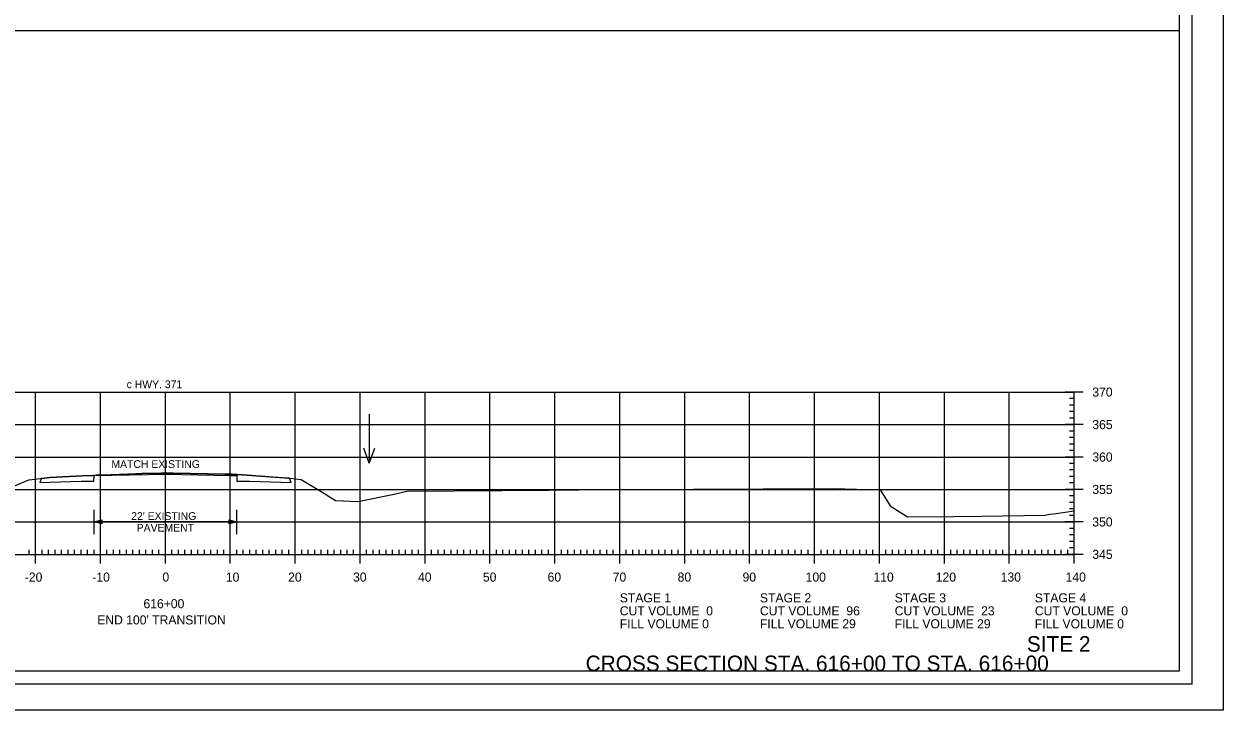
# Model space of a CAD drawing. Extents: x 1368910 to 1369601, y 380116 to 380950.
# Drawn here: x 1369415.8 to 1369600.5, y 380737.1 to 380842.8 of the extents above; entities that cross this region are included whole.
import ezdxf

# ---------------------------------------------------------------- set-up
doc = ezdxf.new("R2010")
doc.units = 0
for name, color, linetype in [('_STAGE 2 CUT', 7, 'Continuous'), ('_STAGE 3 CUT', 7, 'Continuous'), ('Notes', 7, 'Continuous'), ('R_Axis', 7, 'Continuous'), ('R_Axis Annot', 7, 'Continuous'), ('R_Border', 7, 'Continuous'), ('R_Draft', 7, 'Continuous'), ('R_Exist Surface', 7, 'Continuous'), ('R_Grid', 7, 'Continuous'), ('R_No Plot', 7, 'Continuous'), ('R_ROW Annot', 7, 'Continuous'), ('R_Water Annot', 7, 'Continuous')]:
    doc.layers.add(name, color=color, linetype=linetype)

msp = doc.modelspace()

# ---------------------------------------------------------------- linework, layer by layer
at = {"layer": '_STAGE 2 CUT'}
for p, q in [((1369437.59, 380773.62), (1369437.59, 380773.45)), ((1369456.95, 380772.15), (1369456.69, 380772.82))]:
    msp.add_line(p, q, dxfattribs=at)
for points in [[(1369448.57, 380773.41), (1369447.85, 380773.45), (1369447.59, 380773.46), (1369446.77, 380773.48), (1369438.78, 380773.61), (1369437.98, 380773.61), (1369437.69, 380773.62), (1369437.59, 380773.62)], [(1369437.59, 380773.45), (1369447.59, 380773.25), (1369448.59, 380773.23), (1369448.6, 380772.4), (1369450.59, 380772.36), (1369456.95, 380772.15)], [(1369448.57, 380773.4), (1369448.57, 380773.41)], [(1369448.67, 380773.4), (1369448.59, 380773.4), (1369448.57, 380773.4)], [(1369456.69, 380772.82), (1369456.29, 380772.85), (1369450.16, 380773.29), (1369448.67, 380773.4), (1369448.67, 380773.4)]]:
    msp.add_lwpolyline(points, dxfattribs=at)
at = {"layer": '_STAGE 3 CUT'}
for p, q in [((1369437.17, 380773.61), (1369436.89, 380773.61)), ((1369437.3, 380773.61), (1369437.17, 380773.61)), ((1369437.59, 380773.45), (1369437.59, 380773.62)), ((1369418.48, 380772.8), (1369418.23, 380772.15))]:
    msp.add_line(p, q, dxfattribs=at)
for points in [[(1369436.89, 380773.61), (1369433.98, 380773.54), (1369433.01, 380773.5), (1369427.9, 380773.32), (1369426.94, 380773.29), (1369426.53, 380773.27), (1369426.47, 380773.26), (1369424.81, 380773.18), (1369419.8, 380772.94), (1369418.89, 380772.85), (1369418.48, 380772.8)], [(1369437.59, 380773.62), (1369437.38, 380773.62), (1369437.3, 380773.61)], [(1369418.23, 380772.15), (1369424.59, 380772.36), (1369426.58, 380772.4), (1369426.59, 380773.23), (1369437.59, 380773.45)]]:
    msp.add_lwpolyline(points, dxfattribs=at)
at = {"layer": 'R_Axis'}
for p, q in [((1369578.99, 380786.1), (1369576.19, 380786.1)), ((1369577.59, 380785.1), (1369576.89, 380785.1)), ((1369577.59, 380761.1), (1369577.59, 380786.1)), ((1369577.59, 380784.1), (1369576.89, 380784.1)), ((1369577.59, 380783.1), (1369576.89, 380783.1)), ((1369578.99, 380781.1), (1369576.19, 380781.1)), ((1369577.59, 380782.1), (1369576.89, 380782.1)), ((1369577.59, 380780.1), (1369576.89, 380780.1)), ((1369577.59, 380779.1), (1369576.89, 380779.1)), ((1369577.59, 380778.1), (1369576.89, 380778.1)), ((1369578.99, 380776.1), (1369576.19, 380776.1)), ((1369577.59, 380777.1), (1369576.89, 380777.1)), ((1369577.59, 380775.1), (1369576.89, 380775.1)), ((1369577.59, 380774.1), (1369576.89, 380774.1)), ((1369577.59, 380773.1), (1369576.89, 380773.1)), ((1369577.59, 380772.1), (1369576.89, 380772.1)), ((1369578.99, 380771.1), (1369576.19, 380771.1)), ((1369577.59, 380770.1), (1369576.89, 380770.1)), ((1369577.59, 380769.1), (1369576.89, 380769.1)), ((1369577.59, 380768.1), (1369576.89, 380768.1)), ((1369577.59, 380767.1), (1369576.89, 380767.1)), ((1369578.99, 380766.1), (1369576.19, 380766.1)), ((1369577.59, 380765.1), (1369576.89, 380765.1)), ((1369417.59, 380759.7), (1369417.59, 380762.5)), ((1369427.59, 380759.7), (1369427.59, 380762.5)), ((1369437.59, 380759.7), (1369437.59, 380762.5)), ((1369447.59, 380759.7), (1369447.59, 380762.5)), ((1369457.59, 380759.7), (1369457.59, 380762.5)), ((1369467.59, 380759.7), (1369467.59, 380762.5)), ((1369477.59, 380759.7), (1369477.59, 380762.5)), ((1369487.59, 380759.7), (1369487.59, 380762.5)), ((1369497.59, 380759.7), (1369497.59, 380762.5)), ((1369507.59, 380759.7), (1369507.59, 380762.5)), ((1369517.59, 380759.7), (1369517.59, 380762.5)), ((1369527.59, 380759.7), (1369527.59, 380762.5)), ((1369537.59, 380759.7), (1369537.59, 380762.5)), ((1369547.59, 380759.7), (1369547.59, 380762.5)), ((1369557.59, 380759.7), (1369557.59, 380762.5)), ((1369567.59, 380759.7), (1369567.59, 380762.5)), ((1369577.59, 380764.1), (1369576.89, 380764.1)), ((1369577.59, 380763.1), (1369576.89, 380763.1)), ((1369577.59, 380759.7), (1369577.59, 380762.5)), ((1369297.59, 380761.1), (1369577.59, 380761.1)), ((1369416.59, 380761.1), (1369416.59, 380761.8)), ((1369418.59, 380761.1), (1369418.59, 380761.8)), ((1369419.59, 380761.1), (1369419.59, 380761.8)), ((1369420.59, 380761.1), (1369420.59, 380761.8)), ((1369421.59, 380761.1), (1369421.59, 380761.8)), ((1369422.59, 380761.1), (1369422.59, 380761.8)), ((1369423.59, 380761.1), (1369423.59, 380761.8)), ((1369424.59, 380761.1), (1369424.59, 380761.8)), ((1369425.59, 380761.1), (1369425.59, 380761.8)), ((1369426.59, 380761.1), (1369426.59, 380761.8)), ((1369428.59, 380761.1), (1369428.59, 380761.8)), ((1369429.59, 380761.1), (1369429.59, 380761.8)), ((1369430.59, 380761.1), (1369430.59, 380761.8)), ((1369431.59, 380761.1), (1369431.59, 380761.8)), ((1369432.59, 380761.1), (1369432.59, 380761.8)), ((1369433.59, 380761.1), (1369433.59, 380761.8)), ((1369434.59, 380761.1), (1369434.59, 380761.8)), ((1369435.59, 380761.1), (1369435.59, 380761.8)), ((1369436.59, 380761.1), (1369436.59, 380761.8)), ((1369438.59, 380761.1), (1369438.59, 380761.8)), ((1369439.59, 380761.1), (1369439.59, 380761.8)), ((1369440.59, 380761.1), (1369440.59, 380761.8)), ((1369441.59, 380761.1), (1369441.59, 380761.8)), ((1369442.59, 380761.1), (1369442.59, 380761.8)), ((1369443.59, 380761.1), (1369443.59, 380761.8)), ((1369444.59, 380761.1), (1369444.59, 380761.8)), ((1369445.59, 380761.1), (1369445.59, 380761.8)), ((1369446.59, 380761.1), (1369446.59, 380761.8)), ((1369448.59, 380761.1), (1369448.59, 380761.8)), ((1369449.59, 380761.1), (1369449.59, 380761.8)), ((1369450.59, 380761.1), (1369450.59, 380761.8)), ((1369451.59, 380761.1), (1369451.59, 380761.8)), ((1369452.59, 380761.1), (1369452.59, 380761.8)), ((1369453.59, 380761.1), (1369453.59, 380761.8)), ((1369454.59, 380761.1), (1369454.59, 380761.8)), ((1369455.59, 380761.1), (1369455.59, 380761.8)), ((1369456.59, 380761.1), (1369456.59, 380761.8)), ((1369458.59, 380761.1), (1369458.59, 380761.8)), ((1369459.59, 380761.1), (1369459.59, 380761.8)), ((1369460.59, 380761.1), (1369460.59, 380761.8)), ((1369461.59, 380761.1), (1369461.59, 380761.8)), ((1369462.59, 380761.1), (1369462.59, 380761.8)), ((1369463.59, 380761.1), (1369463.59, 380761.8)), ((1369464.59, 380761.1), (1369464.59, 380761.8)), ((1369465.59, 380761.1), (1369465.59, 380761.8)), ((1369466.59, 380761.1), (1369466.59, 380761.8)), ((1369468.59, 380761.1), (1369468.59, 380761.8)), ((1369469.59, 380761.1), (1369469.59, 380761.8)), ((1369470.59, 380761.1), (1369470.59, 380761.8)), ((1369471.59, 380761.1), (1369471.59, 380761.8)), ((1369472.59, 380761.1), (1369472.59, 380761.8)), ((1369473.59, 380761.1), (1369473.59, 380761.8)), ((1369474.59, 380761.1), (1369474.59, 380761.8)), ((1369475.59, 380761.1), (1369475.59, 380761.8)), ((1369476.59, 380761.1), (1369476.59, 380761.8)), ((1369478.59, 380761.1), (1369478.59, 380761.8)), ((1369479.59, 380761.1), (1369479.59, 380761.8)), ((1369480.59, 380761.1), (1369480.59, 380761.8)), ((1369481.59, 380761.1), (1369481.59, 380761.8)), ((1369482.59, 380761.1), (1369482.59, 380761.8)), ((1369483.59, 380761.1), (1369483.59, 380761.8)), ((1369484.59, 380761.1), (1369484.59, 380761.8)), ((1369485.59, 380761.1), (1369485.59, 380761.8)), ((1369486.59, 380761.1), (1369486.59, 380761.8)), ((1369488.59, 380761.1), (1369488.59, 380761.8)), ((1369489.59, 380761.1), (1369489.59, 380761.8)), ((1369490.59, 380761.1), (1369490.59, 380761.8)), ((1369491.59, 380761.1), (1369491.59, 380761.8)), ((1369492.59, 380761.1), (1369492.59, 380761.8)), ((1369493.59, 380761.1), (1369493.59, 380761.8)), ((1369494.59, 380761.1), (1369494.59, 380761.8)), ((1369495.59, 380761.1), (1369495.59, 380761.8)), ((1369496.59, 380761.1), (1369496.59, 380761.8)), ((1369498.59, 380761.1), (1369498.59, 380761.8)), ((1369499.59, 380761.1), (1369499.59, 380761.8)), ((1369500.59, 380761.1), (1369500.59, 380761.8)), ((1369501.59, 380761.1), (1369501.59, 380761.8)), ((1369502.59, 380761.1), (1369502.59, 380761.8)), ((1369503.59, 380761.1), (1369503.59, 380761.8)), ((1369504.59, 380761.1), (1369504.59, 380761.8)), ((1369505.59, 380761.1), (1369505.59, 380761.8)), ((1369506.59, 380761.1), (1369506.59, 380761.8)), ((1369508.59, 380761.1), (1369508.59, 380761.8)), ((1369509.59, 380761.1), (1369509.59, 380761.8)), ((1369510.59, 380761.1), (1369510.59, 380761.8)), ((1369511.59, 380761.1), (1369511.59, 380761.8)), ((1369512.59, 380761.1), (1369512.59, 380761.8)), ((1369513.59, 380761.1), (1369513.59, 380761.8)), ((1369514.59, 380761.1), (1369514.59, 380761.8)), ((1369515.59, 380761.1), (1369515.59, 380761.8)), ((1369516.59, 380761.1), (1369516.59, 380761.8)), ((1369518.59, 380761.1), (1369518.59, 380761.8)), ((1369519.59, 380761.1), (1369519.59, 380761.8)), ((1369520.59, 380761.1), (1369520.59, 380761.8)), ((1369521.59, 380761.1), (1369521.59, 380761.8)), ((1369522.59, 380761.1), (1369522.59, 380761.8)), ((1369523.59, 380761.1), (1369523.59, 380761.8)), ((1369524.59, 380761.1), (1369524.59, 380761.8)), ((1369525.59, 380761.1), (1369525.59, 380761.8)), ((1369526.59, 380761.1), (1369526.59, 380761.8)), ((1369528.59, 380761.1), (1369528.59, 380761.8)), ((1369529.59, 380761.1), (1369529.59, 380761.8)), ((1369530.59, 380761.1), (1369530.59, 380761.8)), ((1369531.59, 380761.1), (1369531.59, 380761.8)), ((1369532.59, 380761.1), (1369532.59, 380761.8)), ((1369533.59, 380761.1), (1369533.59, 380761.8)), ((1369534.59, 380761.1), (1369534.59, 380761.8)), ((1369535.59, 380761.1), (1369535.59, 380761.8)), ((1369536.59, 380761.1), (1369536.59, 380761.8)), ((1369538.59, 380761.1), (1369538.59, 380761.8)), ((1369539.59, 380761.1), (1369539.59, 380761.8)), ((1369540.59, 380761.1), (1369540.59, 380761.8)), ((1369541.59, 380761.1), (1369541.59, 380761.8)), ((1369542.59, 380761.1), (1369542.59, 380761.8)), ((1369543.59, 380761.1), (1369543.59, 380761.8)), ((1369544.59, 380761.1), (1369544.59, 380761.8)), ((1369545.59, 380761.1), (1369545.59, 380761.8)), ((1369546.59, 380761.1), (1369546.59, 380761.8)), ((1369548.59, 380761.1), (1369548.59, 380761.8)), ((1369549.59, 380761.1), (1369549.59, 380761.8)), ((1369550.59, 380761.1), (1369550.59, 380761.8)), ((1369551.59, 380761.1), (1369551.59, 380761.8)), ((1369552.59, 380761.1), (1369552.59, 380761.8)), ((1369553.59, 380761.1), (1369553.59, 380761.8)), ((1369554.59, 380761.1), (1369554.59, 380761.8)), ((1369555.59, 380761.1), (1369555.59, 380761.8)), ((1369556.59, 380761.1), (1369556.59, 380761.8)), ((1369558.59, 380761.1), (1369558.59, 380761.8)), ((1369559.59, 380761.1), (1369559.59, 380761.8)), ((1369560.59, 380761.1), (1369560.59, 380761.8)), ((1369561.59, 380761.1), (1369561.59, 380761.8)), ((1369562.59, 380761.1), (1369562.59, 380761.8)), ((1369563.59, 380761.1), (1369563.59, 380761.8)), ((1369564.59, 380761.1), (1369564.59, 380761.8)), ((1369565.59, 380761.1), (1369565.59, 380761.8)), ((1369566.59, 380761.1), (1369566.59, 380761.8)), ((1369568.59, 380761.1), (1369568.59, 380761.8)), ((1369569.59, 380761.1), (1369569.59, 380761.8)), ((1369570.59, 380761.1), (1369570.59, 380761.8)), ((1369571.59, 380761.1), (1369571.59, 380761.8)), ((1369572.59, 380761.1), (1369572.59, 380761.8)), ((1369573.59, 380761.1), (1369573.59, 380761.8)), ((1369574.59, 380761.1), (1369574.59, 380761.8)), ((1369575.59, 380761.1), (1369575.59, 380761.8)), ((1369578.99, 380761.1), (1369576.19, 380761.1)), ((1369576.59, 380761.1), (1369576.59, 380761.8)), ((1369577.59, 380762.1), (1369576.89, 380762.1))]:
    msp.add_line(p, q, dxfattribs=at)
at = {"layer": 'R_Border'}
for q in [(1369595.77, 380946.56), (1369279.59, 380741.1)]:
    msp.add_line((1369595.77, 380741.1), q, dxfattribs=at)
at = {"layer": 'R_Exist Surface'}
msp.add_lwpolyline([(1369412.14, 380770.75), (1369416.56, 380772.58), (1369417.89, 380772.74), (1369419.8, 380772.94), (1369424.81, 380773.18), (1369426.47, 380773.26), (1369426.53, 380773.27), (1369426.94, 380773.29), (1369427.9, 380773.32), (1369433.01, 380773.5), (1369433.98, 380773.54), (1369437.17, 380773.61), (1369437.38, 380773.62), (1369437.69, 380773.62), (1369437.98, 380773.61), (1369438.78, 380773.61), (1369446.77, 380773.48), (1369447.85, 380773.45), (1369448.57, 380773.41), (1369448.67, 380773.4), (1369448.67, 380773.4), (1369450.16, 380773.29), (1369457.25, 380772.78), (1369457.7, 380772.73), (1369458.51, 380772.64), (1369461.83, 380770.62), (1369463.78, 380769.39), (1369465.01, 380769.36), (1369467.25, 380769.27), (1369473.11, 380770.41), (1369474.8, 380770.85), (1369496.72, 380770.99), (1369505.89, 380771.09), (1369508.17, 380771.11), (1369540.47, 380771.25), (1369547.68, 380771.02), (1369549.26, 380768.58), (1369551.93, 380766.89), (1369559.01, 380766.93), (1369563.36, 380766.99), (1369573.14, 380767.15), (1369573.77, 380767.3), (1369574.8, 380767.4), (1369577.59, 380767.8)], dxfattribs=at)
at = {"layer": 'R_Grid'}
for p, q in [((1369297.59, 380786.1), (1369577.59, 380786.1)), ((1369417.59, 380761.1), (1369417.59, 380786.1)), ((1369427.59, 380761.1), (1369427.59, 380786.1)), ((1369437.59, 380761.1), (1369437.59, 380786.1)), ((1369447.59, 380761.1), (1369447.59, 380786.1)), ((1369457.59, 380761.1), (1369457.59, 380786.1)), ((1369467.59, 380761.1), (1369467.59, 380786.1)), ((1369477.59, 380761.1), (1369477.59, 380786.1)), ((1369487.59, 380761.1), (1369487.59, 380786.1)), ((1369497.59, 380761.1), (1369497.59, 380786.1)), ((1369507.59, 380761.1), (1369507.59, 380786.1)), ((1369517.59, 380761.1), (1369517.59, 380786.1)), ((1369527.59, 380761.1), (1369527.59, 380786.1)), ((1369537.59, 380761.1), (1369537.59, 380786.1)), ((1369547.59, 380761.1), (1369547.59, 380786.1)), ((1369557.59, 380761.1), (1369557.59, 380786.1)), ((1369567.59, 380761.1), (1369567.59, 380786.1)), ((1369577.59, 380761.1), (1369577.59, 380786.1)), ((1369297.59, 380781.1), (1369577.59, 380781.1)), ((1369297.59, 380776.1), (1369577.59, 380776.1)), ((1369297.59, 380771.1), (1369577.59, 380771.1)), ((1369297.59, 380766.1), (1369577.59, 380766.1)), ((1369297.59, 380761.1), (1369577.59, 380761.1))]:
    msp.add_line(p, q, dxfattribs=at)
at = {"layer": 'R_No Plot'}
for points in [[(1369267.18, 380950.45), (1369600.52, 380950.45), (1369600.52, 380737.11), (1369267.18, 380737.11)], [(1369281.59, 380944.56), (1369531.13, 380944.56), (1369531.13, 380934.68), (1369548.67, 380934.68), (1369572.77, 380934.68), (1369572.77, 380912.34), (1369593.77, 380912.34), (1369593.77, 380743.1), (1369281.59, 380743.1)], [(1369281.59, 380841.83), (1369593.77, 380841.83), (1369593.77, 380743.1), (1369281.59, 380743.1)]]:
    msp.add_lwpolyline(points, close=True, dxfattribs=at)
at = {"layer": 'R_ROW Annot'}
for p, q in [((1369426.59, 380764.21), (1369426.59, 380767.98)), ((1369448.59, 380764.21), (1369448.59, 380767.98)), ((1369448.59, 380766.1), (1369426.59, 380766.1))]:
    msp.add_line(p, q, dxfattribs=at)
for points in [[(1369427.79, 380765.8), (1369426.59, 380766.1), (1369427.79, 380766.4)], [(1369447.39, 380766.4), (1369448.59, 380766.1), (1369447.39, 380765.8)]]:
    msp.add_lwpolyline(points, close=True, dxfattribs=at)
at = {"layer": 'R_Water Annot'}
for p, q in [((1369468.99, 380782.69), (1369468.99, 380775.15)), ((1369468.99, 380775.15), (1369468.15, 380777.46)), ((1369468.99, 380775.15), (1369469.83, 380777.46))]:
    msp.add_line(p, q, dxfattribs=at)

# ---------------------------------------------------------------- texts
at = {"layer": 'Notes'}
for s, p in [('c HWY. 371', (1369431.62, 380786.7)), ('MATCH EXISTING', (1369429.27, 380774.41))]:
    msp.add_text(s, height=1.2, dxfattribs=at).set_placement(p)
at = {"layer": 'R_Axis Annot'}
for s, p in [('370', (1369580.39, 380785.4)), ('365', (1369580.39, 380780.4)), ('360', (1369580.39, 380775.4)), ('355', (1369580.39, 380770.4)), ('350', (1369580.39, 380765.4)), ('345', (1369580.39, 380760.4)), ('-20', (1369415.93, 380756.9)), ('-10', (1369426.33, 380756.9)), ('0', (1369437.13, 380756.9)), ('10', (1369446.9, 380756.9)), ('20', (1369456.5, 380756.9)), ('30', (1369466.5, 380756.9)), ('40', (1369476.5, 380756.9)), ('50', (1369486.5, 380756.9)), ('60', (1369496.47, 380756.9)), ('70', (1369506.5, 380756.9)), ('80', (1369516.5, 380756.9)), ('90', (1369526.5, 380756.9)), ('100', (1369536.22, 380756.9)), ('110', (1369546.67, 380756.9)), ('120', (1369556.27, 380756.9)), ('130', (1369566.27, 380756.9)), ('140', (1369576.27, 380756.9)), ('STAGE 1', (1369507.59, 380753.7)), ('STAGE 2', (1369529.18, 380753.7)), ('STAGE 3', (1369549.94, 380753.7)), ('STAGE 4', (1369571.53, 380753.7)), ('616+00', (1369434.21, 380752.8)), ("END 100' TRANSITION", (1369427.08, 380750.3)), ('CUT VOLUME  0', (1369507.59, 380751.7)), ('CUT VOLUME  96', (1369529.18, 380751.7)), ('CUT VOLUME  23', (1369549.94, 380751.7)), ('CUT VOLUME  0', (1369571.53, 380751.7)), ('FILL VOLUME 0', (1369507.59, 380749.7)), ('FILL VOLUME 29', (1369529.18, 380749.7)), ('FILL VOLUME 29', (1369549.94, 380749.7)), ('FILL VOLUME 0', (1369571.53, 380749.7))]:
    msp.add_text(s, height=1.4, dxfattribs=at).set_placement(p)
at = {"layer": 'R_Draft'}
for s, p in [('SITE 2', (1369570.3, 380746.1)), ('CROSS SECTION STA. 616+00 TO STA. 616+00', (1369502.33, 380743.1))]:
    msp.add_text(s, height=2.4, dxfattribs=at).set_placement(p)
at = {"layer": 'R_ROW Annot'}
for s, p in [("22' EXISTING", (1369432.32, 380766.4)), ('PAVEMENT', (1369433.17, 380764.6))]:
    msp.add_text(s, height=1.2, dxfattribs=at).set_placement(p)

doc.saveas('drawing.dxf')
